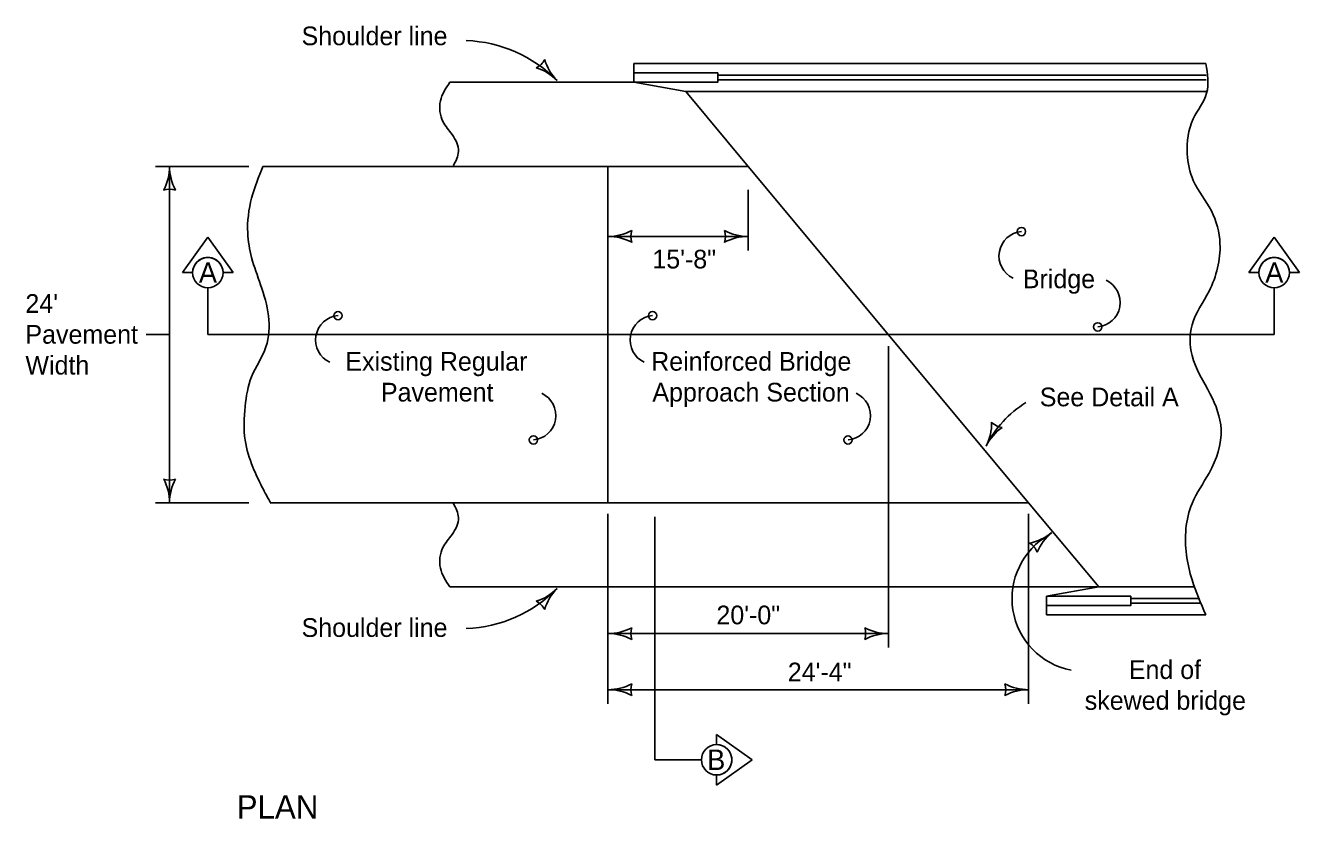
# Model space of a CAD drawing. Extents: x -2134222 to -2124595, y -2139046 to -2134021.
# Drawn here: x -2133964 to -2132873, y -2137780 to -2137101 of the extents above; entities that cross this region are included whole.
import ezdxf

# ---------------------------------------------------------------- set-up
doc = ezdxf.new("R2010")
doc.units = 0
doc.layers.add('BridgeSuperStructureExisting', color=7, linetype='Continuous')
doc.layers.add('dsnStdLabel', color=7, linetype='Continuous')

msp = doc.modelspace()

# ---------------------------------------------------------------- linework, layer by layer
at = {"layer": 'BridgeSuperStructureExisting'}
for p, q in [((-2133443.2, -2137133.4), (-2133443.2, -2137149.4)), ((-2133443.2, -2137133.4), (-2132953.6, -2137133.4)), ((-2133371.2, -2137143.4), (-2132953.3, -2137143.4)), ((-2133600.4, -2137149.4), (-2133443.2, -2137149.4)), ((-2133443.2, -2137149.4), (-2133398.5, -2137157.4)), ((-2133371.2, -2137147.4), (-2132953.2, -2137147.4)), ((-2133398.5, -2137157.4), (-2133345.2, -2137221.4)), ((-2133398.5, -2137157.4), (-2132953, -2137157.4)), ((-2133772.4, -2137221.4), (-2133852.4, -2137221.4)), ((-2133840.4, -2137221.4), (-2133840.4, -2137509.4)), ((-2133760.4, -2137221.4), (-2133345.2, -2137221.4)), ((-2133465.2, -2137509.4), (-2133465.2, -2137221.4)), ((-2133345.2, -2137221.4), (-2133105.2, -2137509.4)), ((-2133345.2, -2137241.4), (-2133345.2, -2137293.4)), ((-2133807.6, -2137282), (-2133829.3, -2137312.4)), ((-2133785.9, -2137312.4), (-2133807.6, -2137282)), ((-2133465.2, -2137281.4), (-2133345.2, -2137281.4)), ((-2132895.1, -2137282), (-2132916.8, -2137312.4)), ((-2132873.4, -2137312.4), (-2132895.1, -2137282)), ((-2133829.3, -2137312.4), (-2133820.6, -2137312.4)), ((-2133794.6, -2137312.4), (-2133785.9, -2137312.4)), ((-2132916.8, -2137312.4), (-2132908.1, -2137312.4)), ((-2132882.1, -2137312.4), (-2132873.4, -2137312.4)), ((-2133807.6, -2137365.4), (-2133807.6, -2137325.4)), ((-2132895.1, -2137365.4), (-2132895.1, -2137325.4)), ((-2133840.4, -2137365.4), (-2133860.4, -2137365.4)), ((-2133767.6, -2137365.4), (-2133807.6, -2137365.4)), ((-2133807.6, -2137365.4), (-2132895.1, -2137365.4)), ((-2133755.6, -2137365.4), (-2133225.2, -2137365.4)), ((-2133465.2, -2137365.4), (-2133465.2, -2137365.4)), ((-2133225.2, -2137365.4), (-2133225.2, -2137365.4)), ((-2133225.2, -2137375.3), (-2133225.2, -2137633.4)), ((-2133772.4, -2137509.4), (-2133852.4, -2137509.4)), ((-2133753.9, -2137509.4), (-2133105.2, -2137509.4)), ((-2133105.2, -2137509.4), (-2133045.2, -2137581.4)), ((-2133465.2, -2137518.8), (-2133465.2, -2137681.4)), ((-2133425.2, -2137521.4), (-2133425.2, -2137729.4)), ((-2133105.2, -2137518.8), (-2133105.2, -2137681.4)), ((-2133600.4, -2137581.4), (-2133045.2, -2137581.4)), ((-2133089.8, -2137589.4), (-2133045.2, -2137581.4)), ((-2133089.8, -2137605.4), (-2133089.8, -2137589.4)), ((-2133045.2, -2137581.4), (-2132963, -2137581.4)), ((-2133017.8, -2137591.4), (-2132959.1, -2137591.4)), ((-2133017.8, -2137595.4), (-2132957.5, -2137595.4)), ((-2133089.8, -2137605.4), (-2132953.6, -2137605.4)), ((-2133465.2, -2137621.4), (-2133225.2, -2137621.4)), ((-2133465.2, -2137669.4), (-2133105.2, -2137669.4)), ((-2133341.8, -2137729.4), (-2133372.2, -2137707.7)), ((-2133372.2, -2137707.7), (-2133372.2, -2137716.4)), ((-2133425.2, -2137729.4), (-2133385.2, -2137729.4)), ((-2133372.2, -2137751), (-2133341.8, -2137729.4)), ((-2133372.2, -2137742.4), (-2133372.2, -2137751))]:
    msp.add_line(p, q, dxfattribs=at)
for points in [[(-2133443.2, -2137149.4), (-2133371.2, -2137149.4), (-2133371.2, -2137141.4), (-2133443.2, -2137141.4)], [(-2133089.8, -2137589.4), (-2133017.8, -2137589.4), (-2133017.8, -2137597.4), (-2133089.8, -2137597.4)]]:
    msp.add_lwpolyline(points, close=True, dxfattribs=at)
for centre in [(-2133111.4, -2137277.2), (-2133696.2, -2137349.2), (-2133427, -2137349.2), (-2133046.1, -2137358.8), (-2133529, -2137455.6), (-2133259.8, -2137455.6)]:
    msp.add_circle(centre, 3.56, dxfattribs=at)
for centre, radius, start, end in [((-2133590.4, -2137228.1), 114.4, 44.4743, 88.005), ((-2133534.1, -2137122.2), 16.7, 296.7409, 332.2076), ((-2133477.9, -2137117.7), 43.2, 196.4018, 224.4743), ((-2133539.6, -2137178.2), 43.2, 44.4743, 72.5468), ((-2133883.5, -2137221.4), 43.2, 331.9275, 360), ((-2133797.2, -2137221.4), 43.2, 180, 208.0725), ((-2133840.4, -2137257.6), 16.7, 72.2666, 107.7334), ((-2133465.2, -2137238.2), 43.2, 270, 298.0725), ((-2133465.2, -2137324.5), 43.2, 61.9275, 90), ((-2133428.9, -2137281.4), 16.7, 162.2666, 197.7334), ((-2133381.4, -2137281.4), 16.7, 342.2666, 17.7333), ((-2133345.2, -2137238.2), 43.2, 241.9275, 270), ((-2133345.2, -2137324.5), 43.2, 90, 118.0725), ((-2133109.6, -2137298.1), 21, 94.9454, 244.904), ((-2133807.6, -2137312.4), 13, 359.9948, 180.0052), ((-2133807.6, -2137312.4), 13, 0.0052, 179.9948), ((-2132895.1, -2137312.4), 13, 359.9948, 180.0052), ((-2132895.1, -2137312.4), 13, 0.0052, 179.9948), ((-2133807.6, -2137312.4), 13, 180.0052, 359.9948), ((-2133047.9, -2137337.9), 21, 274.9454, 64.904), ((-2132895.1, -2137312.4), 13, 180.0052, 359.9948), ((-2133694.4, -2137370.1), 21, 94.9454, 244.904), ((-2133425.2, -2137370.1), 21, 94.9454, 244.904), ((-2133530.8, -2137434.7), 21, 274.9454, 64.904), ((-2133261.6, -2137434.7), 21, 274.9454, 64.904), ((-2133057.9, -2137503), 93.7, 122.0014, 153.2508), ((-2133180.1, -2137441.4), 43.2, 333.2508, 1.3233), ((-2133103, -2137480.2), 43.2, 125.1784, 153.2508), ((-2133125.3, -2137428.5), 16.7, 225.5175, 260.9842), ((-2133840.4, -2137473.2), 16.7, 252.2666, 287.7333), ((-2133883.5, -2137509.4), 43.2, 360, 28.0725), ((-2133797.2, -2137509.4), 43.2, 151.9275, 180), ((-2133056.7, -2137591.3), 62.7, 119.4281, 258.7764), ((-2133112.9, -2137501.6), 43.2, 281.3557, 309.4281), ((-2133058.1, -2137568.3), 43.2, 129.4281, 157.5006), ((-2133113.4, -2137557.9), 16.7, 21.6948, 57.1615), ((-2133590.4, -2137502.6), 114.4, 271.995, 315.5257), ((-2133539.6, -2137552.5), 43.2, 287.4532, 315.5257), ((-2133477.9, -2137613), 43.2, 135.5257, 163.5982), ((-2133534.1, -2137608.6), 16.7, 27.7924, 63.2591), ((-2133465.2, -2137578.2), 43.2, 270, 298.0725), ((-2133465.2, -2137664.5), 43.2, 61.9275, 90), ((-2133428.9, -2137621.4), 16.7, 162.2666, 197.7334), ((-2133261.4, -2137621.4), 16.7, 342.2666, 17.7333), ((-2133225.2, -2137578.2), 43.2, 241.9275, 270), ((-2133225.2, -2137664.5), 43.2, 90, 118.0725), ((-2133465.2, -2137626.2), 43.2, 270, 298.0725), ((-2133428.9, -2137669.4), 16.7, 162.2666, 197.7334), ((-2133141.4, -2137669.4), 16.7, 342.2666, 17.7333), ((-2133105.2, -2137626.2), 43.2, 241.9275, 270), ((-2133465.2, -2137712.5), 43.2, 61.9275, 90), ((-2133105.2, -2137712.5), 43.2, 90, 118.0725), ((-2133372.2, -2137729.4), 13, 90.0052, 269.9948), ((-2133372.2, -2137729.4), 13, 269.9948, 90.0052), ((-2133372.2, -2137729.4), 13, 270.0052, 89.9948)]:
    msp.add_arc(centre, radius, start, end, dxfattribs=at)
for points in [[(-2132953.6, -2137605.4), (-2132965.4, -2137575.4), (-2132970.6, -2137531.7), (-2132965.4, -2137509.9), (-2132950.8, -2137483.9), (-2132940.5, -2137446.5), (-2132949.8, -2137416.4), (-2132965.4, -2137383.2), (-2132965.4, -2137357.2), (-2132950.8, -2137328.1), (-2132941.5, -2137287.6), (-2132948.8, -2137259.5), (-2132964.3, -2137233.6), (-2132969.5, -2137210.7), (-2132964.3, -2137180.6), (-2132952.9, -2137158.8), (-2132953.6, -2137133.4)], [(-2133600.4, -2137149.4), (-2133608.6, -2137165.4), (-2133606.4, -2137183.1), (-2133598.6, -2137194.2), (-2133593.1, -2137208.6), (-2133597.5, -2137220.8)], [(-2133760.4, -2137221.4), (-2133770.1, -2137248.5), (-2133773.5, -2137278.4), (-2133770.1, -2137299.5), (-2133762.4, -2137322.8), (-2133755.7, -2137349.4), (-2133757.9, -2137376), (-2133770.1, -2137401.5), (-2133775.7, -2137426.9), (-2133775.7, -2137455.8), (-2133769, -2137479), (-2133761.3, -2137495.7), (-2133753.5, -2137510.1)], [(-2133600.4, -2137581.4), (-2133608.6, -2137565.3), (-2133606.4, -2137547.6), (-2133598.6, -2137536.5), (-2133593.1, -2137522.1), (-2133597.5, -2137509.9)]]:
    msp.add_spline(points, degree=3, dxfattribs=at)

# ---------------------------------------------------------------- texts
at = {"layer": 'dsnStdLabel'}
for s, height, p in [('Shoulder line', 16, (-2133727.4, -2137117.7)), ('15\'-8"', 16, (-2133427.2, -2137308.8)), ('A', 17.5, (-2133815.3, -2137321.1)), ('A', 17.5, (-2132902.8, -2137321.1)), ('Bridge', 16, (-2133110.2, -2137325.7)), ("24'", 16, (-2133963.7, -2137346.8)), ('Pavement', 16, (-2133963.7, -2137373.2)), ('Width', 16, (-2133963.7, -2137399.6)), ('Existing Regular', 16, (-2133689.9, -2137396.3)), ('Reinforced Bridge', 16, (-2133428.2, -2137396.3)), ('Approach Section', 16, (-2133427.2, -2137422.7)), ('Pavement', 16, (-2133659.5, -2137422.7)), ('See Detail A', 16, (-2133095.7, -2137426.8)), ('20\'-0"', 16, (-2133372.4, -2137613.4)), ('Shoulder line', 16, (-2133727.4, -2137624.2)), ('24\'-4"', 16, (-2133311.3, -2137662.2)), ('End of', 16, (-2133019.5, -2137660.2)), ('skewed bridge', 16, (-2133057.2, -2137686.6)), ('B', 17.5, (-2133380.4, -2137738.1)), ('PLAN', 20, (-2133782.9, -2137779.7))]:
    msp.add_text(s, height=height, dxfattribs=at).set_placement(p)

doc.saveas('drawing.dxf')
